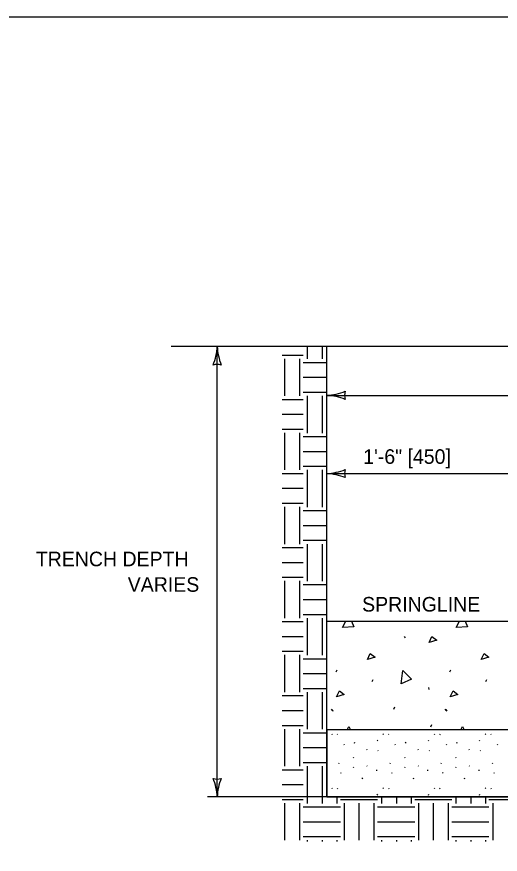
# Model space of a CAD drawing. Extents: x 49991.4 to 50061.4, y 49960.6 to 50011.4.
# Drawn here: x 50005.349 to 50007.338, y 49995.554 to 49998.999 of the extents above; entities that cross this region are included whole.
import ezdxf

# ---------------------------------------------------------------- set-up
doc = ezdxf.new("R2010")
doc.units = 0
for name, color, linetype in [('Level 1', 7, 'Continuous'), ('Level 2', 7, 'Continuous'), ('Level 3', 7, 'Continuous')]:
    doc.layers.add(name, color=color, linetype=linetype)

msp = doc.modelspace()

# ---------------------------------------------------------------- linework, layer by layer
at = {"layer": 'Level 1'}
for p, q in [((50009.8078, 49997.6424), (50005.9845, 49997.6424)), ((50006.5441, 49997.6424), (50006.5441, 49997.5913)), ((50006.6053, 49997.6424), (50006.6053, 49997.5913)), ((50006.6247, 49995.7899), (50006.6247, 49997.6424)), ((50006.4413, 49997.6076), (50006.5277, 49997.6076)), ((50006.4513, 49997.5923), (50006.4513, 49997.4395)), ((50006.5124, 49997.5923), (50006.5124, 49997.4395)), ((50006.5277, 49997.5771), (50006.6247, 49997.5771)), ((50006.5277, 49997.5159), (50006.6247, 49997.5159)), ((50006.5277, 49997.4548), (50006.6247, 49997.4548)), ((50006.4413, 49997.4252), (50006.5277, 49997.4252)), ((50006.5441, 49997.4395), (50006.5441, 49997.2866)), ((50006.6053, 49997.4395), (50006.6053, 49997.2866)), ((50006.4413, 49997.3641), (50006.5277, 49997.3641)), ((50006.4413, 49997.3029), (50006.5277, 49997.3029)), ((50006.4513, 49997.2877), (50006.4513, 49997.1348)), ((50006.5124, 49997.2877), (50006.5124, 49997.1348)), ((50006.5277, 49997.2724), (50006.6247, 49997.2724)), ((50006.5277, 49997.2112), (50006.6247, 49997.2112)), ((50006.5277, 49997.1501), (50006.6247, 49997.1501)), ((50006.4413, 49997.1205), (50006.5277, 49997.1205)), ((50006.5441, 49997.1348), (50006.5441, 49996.9819)), ((50006.6053, 49997.1348), (50006.6053, 49996.9819)), ((50006.4413, 49997.0594), (50006.5277, 49997.0594)), ((50006.4413, 49996.9982), (50006.5277, 49996.9982)), ((50006.4513, 49996.983), (50006.4513, 49996.8301)), ((50006.5124, 49996.983), (50006.5124, 49996.8301)), ((50006.5277, 49996.9677), (50006.6247, 49996.9677)), ((50006.5277, 49996.9065), (50006.6247, 49996.9065)), ((50006.5277, 49996.8454), (50006.6247, 49996.8454)), ((50006.5441, 49996.8301), (50006.5441, 49996.6772)), ((50006.6053, 49996.8301), (50006.6053, 49996.6772)), ((50006.4413, 49996.8159), (50006.5277, 49996.8159)), ((50006.4413, 49996.7547), (50006.5277, 49996.7547)), ((50006.4413, 49996.6935), (50006.5277, 49996.6935)), ((50006.4513, 49996.6783), (50006.4513, 49996.5254)), ((50006.5124, 49996.6783), (50006.5124, 49996.5254)), ((50006.5277, 49996.663), (50006.6247, 49996.663)), ((50006.5277, 49996.6018), (50006.6247, 49996.6018)), ((50006.5277, 49996.5407), (50006.6247, 49996.5407)), ((50006.5441, 49996.5254), (50006.5441, 49996.3725)), ((50006.6053, 49996.5254), (50006.6053, 49996.3725)), ((50006.4413, 49996.5112), (50006.5277, 49996.5112)), ((50006.6247, 49996.5122), (50007.4493, 49996.5122)), ((50006.6893, 49996.4861), (50006.7031, 49996.5122)), ((50007.1573, 49996.4861), (50007.171, 49996.5122)), ((50006.4413, 49996.45), (50006.5277, 49996.45)), ((50006.9433, 49996.45), (50006.9472, 49996.4441)), ((50006.4413, 49996.3889), (50006.5277, 49996.3889)), ((50006.4513, 49996.3736), (50006.4513, 49996.2207)), ((50006.5124, 49996.3736), (50006.5124, 49996.2207)), ((50006.5277, 49996.3583), (50006.6247, 49996.3583)), ((50006.663, 49996.3044), (50006.6669, 49996.3132)), ((50007.1309, 49996.3044), (50007.1348, 49996.3132)), ((50006.5277, 49996.2971), (50006.6247, 49996.2971)), ((50006.8114, 49996.2644), (50006.8154, 49996.2732)), ((50007.2794, 49996.2644), (50007.2833, 49996.2732)), ((50006.4413, 49996.2065), (50006.5277, 49996.2065)), ((50006.5277, 49996.236), (50006.6247, 49996.236)), ((50006.5441, 49996.2207), (50006.5441, 49996.0678)), ((50006.6053, 49996.2207), (50006.6053, 49996.0678)), ((50007.0437, 49996.2398), (50007.0447, 49996.231)), ((50006.4413, 49996.1453), (50006.5277, 49996.1453)), ((50006.6424, 49996.1511), (50006.6464, 49996.1452)), ((50006.6464, 49996.1488), (50006.6503, 49996.143)), ((50006.9003, 49996.1511), (50006.9042, 49996.1599)), ((50007.1104, 49996.1511), (50007.1143, 49996.1452)), ((50007.1143, 49996.1488), (50007.1182, 49996.143)), ((50006.4413, 49996.0842), (50006.5277, 49996.0842)), ((50006.4513, 49996.0689), (50006.4513, 49995.916)), ((50006.5124, 49996.0689), (50006.5124, 49995.916)), ((50007.0527, 49996.0787), (50007.0566, 49996.0874)), ((50006.5277, 49996.0536), (50006.6247, 49996.0536)), ((50006.6247, 49996.0653), (50006.6247, 49995.7899)), ((50009.1677, 49996.0653), (50006.6247, 49996.0653)), ((50006.6455, 49996.0493), (50006.6471, 49996.0469)), ((50006.6681, 49996.0484), (50006.6696, 49996.046)), ((50006.856, 49996.0493), (50006.8576, 49996.0469)), ((50006.8785, 49996.0484), (50006.8801, 49996.046)), ((50007.0664, 49996.0493), (50007.068, 49996.0469)), ((50007.089, 49996.0484), (50007.0906, 49996.046)), ((50007.2769, 49996.0493), (50007.2785, 49996.0469)), ((50007.2994, 49996.0484), (50007.301, 49996.046)), ((50006.6946, 49996.0063), (50006.6962, 49996.0039)), ((50006.7389, 49996.0109), (50006.7405, 49996.0144)), ((50006.8326, 49996.02), (50006.8342, 49996.0235)), ((50006.9051, 49996.0063), (50006.9066, 49996.0039)), ((50006.9493, 49996.0109), (50006.9509, 49996.0144)), ((50007.0431, 49996.02), (50007.0447, 49996.0235)), ((50007.1155, 49996.0063), (50007.1171, 49996.0039)), ((50007.1598, 49996.0109), (50007.1614, 49996.0144)), ((50007.2535, 49996.02), (50007.2551, 49996.0235)), ((50007.326, 49996.0063), (50007.3275, 49996.0039)), ((50006.5277, 49995.9924), (50006.6247, 49995.9924)), ((50006.6247, 49995.9813), (50006.6262, 49995.9789)), ((50006.7883, 49995.9856), (50006.7899, 49995.9832)), ((50006.8351, 49995.9813), (50006.8367, 49995.9789)), ((50006.9988, 49995.9856), (50007.0004, 49995.9832)), ((50007.0455, 49995.9813), (50007.0471, 49995.9789)), ((50007.2092, 49995.9856), (50007.2108, 49995.9832)), ((50007.256, 49995.9813), (50007.2576, 49995.9789)), ((50006.5277, 49995.9313), (50006.6247, 49995.9313)), ((50006.7336, 49995.9532), (50006.7352, 49995.9508)), ((50006.9441, 49995.9532), (50006.9457, 49995.9508)), ((50007.1545, 49995.9532), (50007.1561, 49995.9508)), ((50006.4413, 49995.9018), (50006.5277, 49995.9018)), ((50006.5441, 49995.916), (50006.5441, 49995.7631)), ((50006.6053, 49995.916), (50006.6053, 49995.7631)), ((50006.6748, 49995.9266), (50006.6764, 49995.9302)), ((50006.7349, 49995.9104), (50006.7365, 49995.914)), ((50006.7898, 49995.9181), (50006.7914, 49995.9157)), ((50006.829, 49995.9005), (50006.8294, 49995.8969)), ((50006.8852, 49995.9266), (50006.8868, 49995.9302)), ((50006.9454, 49995.9104), (50006.947, 49995.914)), ((50007.0003, 49995.9181), (50007.0019, 49995.9157)), ((50007.0394, 49995.9005), (50007.0398, 49995.8969)), ((50007.0957, 49995.9266), (50007.0973, 49995.9302)), ((50007.1558, 49995.9104), (50007.1574, 49995.914)), ((50007.2107, 49995.9181), (50007.2123, 49995.9157)), ((50007.2499, 49995.9005), (50007.2503, 49995.8969)), ((50007.3062, 49995.9266), (50007.3077, 49995.9302)), ((50006.6806, 49995.89), (50006.6821, 49995.8876)), ((50006.7709, 49995.8645), (50006.7725, 49995.8681)), ((50006.891, 49995.89), (50006.8926, 49995.8876)), ((50006.9814, 49995.8645), (50006.983, 49995.8681)), ((50007.1015, 49995.89), (50007.103, 49995.8876)), ((50007.1918, 49995.8645), (50007.1934, 49995.8681)), ((50007.3119, 49995.89), (50007.3135, 49995.8876)), ((50006.4413, 49995.8406), (50006.5277, 49995.8406)), ((50006.6455, 49995.8267), (50006.6471, 49995.8243)), ((50006.6681, 49995.8258), (50006.6696, 49995.8234)), ((50006.8326, 49995.7974), (50006.8342, 49995.8009)), ((50006.856, 49995.8267), (50006.8576, 49995.8243)), ((50006.8785, 49995.8258), (50006.8801, 49995.8234)), ((50007.0431, 49995.7974), (50007.0447, 49995.8009)), ((50007.0664, 49995.8267), (50007.068, 49995.8243)), ((50007.089, 49995.8258), (50007.0906, 49995.8234)), ((50007.2535, 49995.7974), (50007.2551, 49995.8009)), ((50007.2769, 49995.8267), (50007.2785, 49995.8243)), ((50007.2994, 49995.8258), (50007.301, 49995.8234)), ((50006.4413, 49995.7795), (50006.5277, 49995.7795)), ((50006.4513, 49995.7642), (50006.4513, 49995.6113)), ((50006.5124, 49995.7642), (50006.5124, 49995.6113)), ((50009.1677, 49995.7899), (50006.6247, 49995.7899)), ((50006.6247, 49995.7899), (50009.1677, 49995.7899)), ((50006.6665, 49995.7899), (50006.6665, 49995.7631)), ((50006.6806, 49995.7795), (50006.8335, 49995.7795)), ((50006.6959, 49995.7642), (50006.6959, 49995.6113)), ((50006.7396, 49995.7899), (50006.7405, 49995.7918)), ((50006.7571, 49995.7642), (50006.7571, 49995.6113)), ((50006.8182, 49995.7642), (50006.8182, 49995.6113)), ((50006.8499, 49995.7899), (50006.8499, 49995.7631)), ((50006.9111, 49995.7899), (50006.9111, 49995.7631)), ((50006.9501, 49995.7899), (50006.9509, 49995.7918)), ((50006.9722, 49995.7899), (50006.9722, 49995.7631)), ((50006.9864, 49995.7795), (50007.1393, 49995.7795)), ((50007.0017, 49995.7642), (50007.0017, 49995.6113)), ((50007.0628, 49995.7642), (50007.0628, 49995.6113)), ((50007.124, 49995.7642), (50007.124, 49995.6113)), ((50007.1557, 49995.7899), (50007.1557, 49995.7631)), ((50007.1605, 49995.7899), (50007.1614, 49995.7918)), ((50007.2168, 49995.7899), (50007.2168, 49995.7631)), ((50007.278, 49995.7899), (50007.278, 49995.7631)), ((50007.2921, 49995.7795), (50007.445, 49995.7795)), ((50007.3074, 49995.7642), (50007.3074, 49995.6113)), ((50006.5277, 49995.7489), (50006.6806, 49995.7489)), ((50006.8335, 49995.7489), (50006.9864, 49995.7489)), ((50007.1393, 49995.7489), (50007.2921, 49995.7489)), ((50006.5277, 49995.6877), (50006.6806, 49995.6877)), ((50006.8335, 49995.6877), (50006.9864, 49995.6877)), ((50007.1393, 49995.6877), (50007.2921, 49995.6877)), ((50006.5277, 49995.6266), (50006.6806, 49995.6266)), ((50006.8335, 49995.6266), (50006.9864, 49995.6266)), ((50007.1393, 49995.6266), (50007.2921, 49995.6266)), ((50006.5441, 49995.6113), (50006.5441, 49995.6066)), ((50006.6053, 49995.6113), (50006.6053, 49995.6066)), ((50006.6665, 49995.6113), (50006.6665, 49995.6066)), ((50006.8499, 49995.6113), (50006.8499, 49995.6066)), ((50006.9111, 49995.6113), (50006.9111, 49995.6066)), ((50006.9722, 49995.6113), (50006.9722, 49995.6066)), ((50007.1557, 49995.6113), (50007.1557, 49995.6066)), ((50007.2168, 49995.6113), (50007.2168, 49995.6066)), ((50007.278, 49995.6113), (50007.278, 49995.6066))]:
    msp.add_line(p, q, dxfattribs=at)
msp.add_lwpolyline([(49999.3835, 49998.9992), (50016.7501, 49998.9992), (50016.7501, 49987.7988), (49999.3835, 49987.7988)], close=True, dxfattribs=at)
for points in [[(50006.7263, 49996.5122), (50006.7362, 49996.49), (50006.6903, 49996.4861)], [(50007.1943, 49996.5122), (50007.2041, 49996.49), (50007.1582, 49996.4861)], [(50007.0459, 49996.4246), (50007.0576, 49996.449), (50007.0771, 49996.4343), (50007.0459, 49996.4246)], [(50006.7921, 49996.3547), (50006.8038, 49996.3792), (50006.8234, 49996.3645), (50006.7921, 49996.3547)], [(50007.26, 49996.3547), (50007.2717, 49996.3792), (50007.2913, 49996.3645), (50007.26, 49996.3547)], [(50006.9303, 49996.2543), (50006.938, 49996.3101), (50006.973, 49996.274), (50006.9312, 49996.2546)], [(50006.6649, 49996.2019), (50006.6766, 49996.2263), (50006.6962, 49996.2116), (50006.6649, 49996.2019)], [(50007.1328, 49996.2019), (50007.1446, 49996.2263), (50007.1641, 49996.2116), (50007.1328, 49996.2019)], [(50006.7081, 49996.0653), (50006.7157, 49996.0796), (50006.7221, 49996.0653)], [(50007.176, 49996.0653), (50007.1836, 49996.0796), (50007.19, 49996.0653)]]:
    msp.add_lwpolyline(points, dxfattribs=at)
at = {"layer": 'Level 3'}
for p, q in [((50006.174, 49995.7899), (50006.174, 49997.6424)), ((50006.6247, 49997.4417), (50009.1677, 49997.4417)), ((50006.6247, 49997.1199), (50007.4493, 49997.1199)), ((50006.6247, 49995.7899), (50006.134, 49995.7899))]:
    msp.add_line(p, q, dxfattribs=at)
for centre, radius, start, end in [((50005.9519, 49997.6515), 0.2223, 337.456, 357.6395), ((50006.4067, 49997.6539), 0.233, 182.8273, 202.0772), ((50006.174, 49997.5141), 0.0548, 72.1388, 107.8612), ((50006.6132, 49997.6744), 0.233, 272.8273, 292.0772), ((50006.7529, 49997.4417), 0.0548, 162.1388, 197.8612), ((50006.6155, 49997.2196), 0.2223, 67.456, 87.6395), ((50006.6132, 49997.3526), 0.233, 272.8273, 292.0772), ((50006.7529, 49997.1199), 0.0548, 162.1388, 197.8612), ((50006.6155, 49996.8978), 0.2223, 67.456, 87.6395), ((50006.174, 49995.9181), 0.0548, 252.1388, 287.8612), ((50005.9413, 49995.7784), 0.233, 2.8273, 22.0772), ((50006.3962, 49995.7807), 0.2223, 157.456, 177.6395)]:
    msp.add_arc(centre, radius, start, end, dxfattribs=at)

# ---------------------------------------------------------------- texts
at = {"layer": 'Level 2'}
for s, p in [('1\'-6" [450]', (50006.7749, 49997.1599)), ('TRENCH DEPTH', (50005.4278, 49996.7386)), ('VARIES', (50005.8061, 49996.6336)), ('SPRINGLINE', (50006.7702, 49996.5522))]:
    msp.add_text(s, height=0.06, dxfattribs=at).set_placement(p)

doc.saveas('drawing.dxf')
